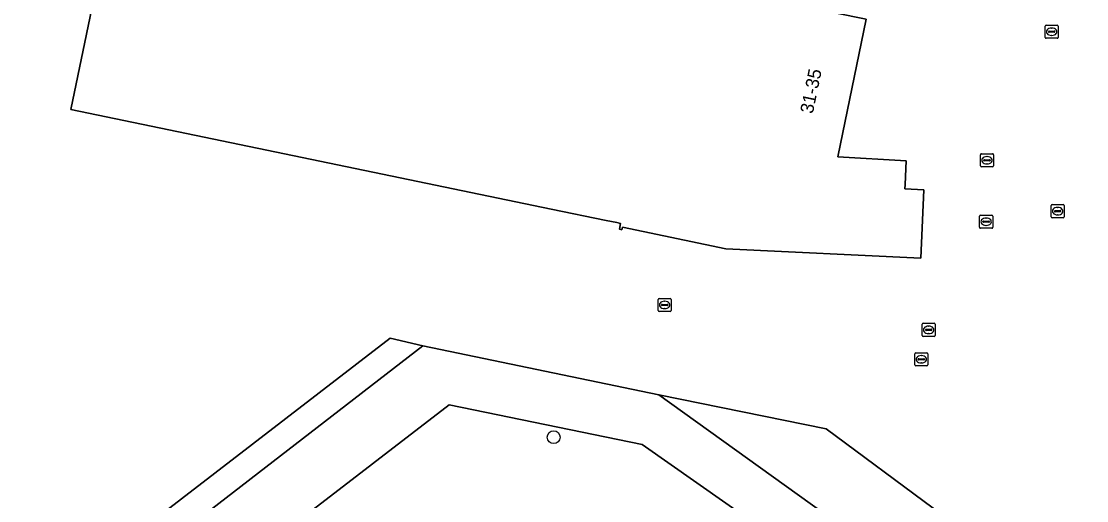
# Model space of a CAD drawing. Extents: x 157692 to 159674, y 381452 to 383291.
# Drawn here: x 158655.2 to 158736.3, y 381918.9 to 381955.5 of the extents above; entities that cross this region are included whole.
import ezdxf

# ---------------------------------------------------------------- set-up
doc = ezdxf.new("R2010")
doc.units = 0
for name, color, linetype in [('IMGEO_Boom', 7, 'Continuous'), ('IMGEO_Brandkraan', 7, 'Continuous'), ('IMGEO_Erf', 7, 'Continuous'), ('IMGEO_Groenvoorziening', 7, 'Continuous'), ('IMGEO_Hek', 7, 'Continuous'), ('IMGEO_Kolk', 7, 'Continuous'), ('IMGEO_Pand', 7, 'Continuous'), ('IMGEO_Pand_nummerreeks', 7, 'Continuous'), ('IMGEO_Rioolput', 7, 'Continuous'), ('IMGEO_Waterloop', 7, 'Continuous')]:
    doc.layers.add(name, color=color, linetype=linetype)

msp = doc.modelspace()

# ---------------------------------------------------------------- linework, layer by layer
at = {"layer": 'IMGEO_Boom'}
msp.add_circle((158695.725, 381923.769), 0.489, dxfattribs=at)
at = {"layer": 'IMGEO_Brandkraan'}
for p, q in [((158733.631, 381940.573), (158733.631, 381941.425)), ((158733.706, 381941.499), (158734.558, 381941.499)), ((158734.632, 381941.425), (158734.632, 381940.573)), ((158734.558, 381940.499), (158733.706, 381940.499)), ((158733.89, 381940.993), (158733.89, 381941.005)), ((158734.328, 381940.956), (158733.93, 381940.956)), ((158733.933, 381941.042), (158734.331, 381941.042)), ((158734.142, 381940.719), (158734.117, 381940.719)), ((158734.119, 381941.279), (158734.144, 381941.279)), ((158734.374, 381941.005), (158734.374, 381940.993))]:
    msp.add_line(p, q, dxfattribs=at)
for points in [[(158733.631, 381940.573), (158733.631, 381941.425)], [(158733.706, 381941.499), (158734.558, 381941.499)], [(158734.632, 381941.425), (158734.632, 381940.573)], [(158734.558, 381940.499), (158733.706, 381940.499)]]:
    msp.add_lwpolyline(points, dxfattribs=at)
for centre, radius, start, end in [((158733.708, 381941.423), 0.0765, 91.55205, 178.44795), ((158733.708, 381941.423), 0.0765, 91.55205, 178.44795), ((158734.556, 381941.423), 0.0765, 1.55205, 88.44795), ((158734.556, 381941.423), 0.0765, 1.55205, 88.44795), ((158733.708, 381940.575), 0.0765, 181.55205, 268.44795), ((158733.708, 381940.575), 0.0765, 181.55205, 268.44795), ((158733.93, 381941.002), 0.0403, 85.87752, 175.75265), ((158733.927, 381940.992), 0.0366, 178.93798, 274.71019), ((158734.331, 381940.999), 0.043, 264.86636, 352.45326), ((158734.335, 381941.004), 0.0386, 1.73085, 96.63898), ((158734.556, 381940.575), 0.0765, 271.55205, 358.44795), ((158734.556, 381940.575), 0.0765, 271.55205, 358.44795)]:
    msp.add_arc(centre, radius, start, end, dxfattribs=at)
for centre, major_axis, ratio, start_param, end_param in [((158734.118, 381940.999), (-0.387, 0.002), 0.722429, 4.712389, 7.853982), ((158734.143, 381940.999), (-0.39, 0.002), 0.717154, 1.570796, 4.712389)]:
    msp.add_ellipse(centre, major_axis=major_axis, ratio=ratio, start_param=start_param, end_param=end_param, dxfattribs=at)
at = {"layer": 'IMGEO_Erf'}
msp.add_lwpolyline([(158664.128, 381973.71), (158713.569, 381963.436), (158712.251, 381957.142), (158719.537, 381955.629), (158717.381, 381945.141), (158722.597, 381944.826), (158722.505, 381943.036), (158722.488, 381942.706), (158723.939, 381942.615), (158723.695, 381937.426), (158708.841, 381938.136), (158700.971, 381939.766), (158700.93, 381939.582), (158700.735, 381939.627), (158700.816, 381940.064), (158700.532, 381940.123), (158699.728, 381940.29), (158695.533, 381941.16), (158658.933, 381948.752)], close=True, dxfattribs=at)
msp.add_lwpolyline([(158624.725, 381886.233), (158683.269, 381931.316), (158685.758, 381930.737), (158703.73, 381926.995), (158716.491, 381924.398), (158724.647, 381918.357), (158745.17, 381903.414), (158763.626, 381917.95), (158795.014, 381942.671), (158804.708, 381950.306)], dxfattribs=at)
at = {"layer": 'IMGEO_Groenvoorziening'}
msp.add_lwpolyline([(158776.423, 381922.752), (158777.324, 381922.523), (158780.275, 381921.775), (158784.698, 381920.653), (158797.869, 381940.663), (158795.619, 381940.468), (158786.617, 381934.019), (158754.359, 381908.504), (158745.892, 381902.253), (158742.29, 381899.292), (158742.662, 381899.025), (158742.172, 381897.333), (158740.224, 381896.745), (158702.48, 381923.203), (158687.769, 381926.237), (158618.962, 381873.281)], dxfattribs=at)
for points in [[(158586.402, 381853.577), (158585.982, 381856.018), (158594.838, 381861.745), (158603.993, 381868.033), (158633.512, 381890.366), (158685.758, 381930.737), (158683.269, 381931.316), (158624.725, 381886.233), (158606.244, 381872.139), (158601.416, 381868.614), (158584.118, 381856.969)], [(158745.17, 381903.414), (158724.647, 381918.357), (158716.491, 381924.398), (158703.73, 381926.995), (158742.29, 381899.292)]]:
    msp.add_lwpolyline(points, close=True, dxfattribs=at)
at = {"layer": 'IMGEO_Hek'}
msp.add_lwpolyline([(158624.725, 381886.233), (158683.269, 381931.316)], dxfattribs=at)
at = {"layer": 'IMGEO_Kolk'}
for p, q in [((158733.174, 381954.248), (158733.174, 381955.1)), ((158733.249, 381955.174), (158734.101, 381955.174)), ((158734.175, 381955.1), (158734.175, 381954.248)), ((158733.433, 381954.668), (158733.433, 381954.68)), ((158733.871, 381954.631), (158733.473, 381954.631)), ((158733.476, 381954.717), (158733.874, 381954.717)), ((158733.685, 381954.394), (158733.66, 381954.394)), ((158733.662, 381954.954), (158733.687, 381954.954)), ((158733.917, 381954.68), (158733.917, 381954.668)), ((158734.101, 381954.174), (158733.249, 381954.174)), ((158728.182, 381939.766), (158728.182, 381940.618)), ((158728.257, 381940.692), (158729.109, 381940.692)), ((158728.67, 381940.472), (158728.695, 381940.472)), ((158729.183, 381940.618), (158729.183, 381939.766)), ((158729.109, 381939.692), (158728.257, 381939.692)), ((158728.441, 381940.186), (158728.441, 381940.198)), ((158728.879, 381940.149), (158728.481, 381940.149)), ((158728.484, 381940.235), (158728.882, 381940.235)), ((158728.693, 381939.912), (158728.668, 381939.912)), ((158728.925, 381940.198), (158728.925, 381940.186)), ((158703.684, 381933.423), (158703.684, 381934.275)), ((158703.759, 381934.349), (158704.611, 381934.349)), ((158704.172, 381934.129), (158704.197, 381934.129)), ((158704.685, 381934.275), (158704.685, 381933.423)), ((158704.611, 381933.349), (158703.759, 381933.349)), ((158703.943, 381933.843), (158703.943, 381933.855)), ((158704.381, 381933.806), (158703.983, 381933.806)), ((158703.986, 381933.892), (158704.384, 381933.892)), ((158704.195, 381933.569), (158704.17, 381933.569)), ((158704.427, 381933.855), (158704.427, 381933.843)), ((158723.24, 381929.278), (158723.24, 381930.13)), ((158723.315, 381930.204), (158724.167, 381930.204)), ((158723.728, 381929.984), (158723.753, 381929.984)), ((158724.241, 381930.13), (158724.241, 381929.278)), ((158724.167, 381929.204), (158723.315, 381929.204)), ((158723.499, 381929.698), (158723.499, 381929.71)), ((158723.937, 381929.661), (158723.539, 381929.661)), ((158723.542, 381929.747), (158723.94, 381929.747)), ((158723.751, 381929.424), (158723.726, 381929.424)), ((158723.983, 381929.71), (158723.983, 381929.698))]:
    msp.add_line(p, q, dxfattribs=at)
for points in [[(158733.174, 381954.248), (158733.174, 381955.1)], [(158733.249, 381955.174), (158734.101, 381955.174)], [(158734.175, 381955.1), (158734.175, 381954.248)], [(158734.101, 381954.174), (158733.249, 381954.174)], [(158728.182, 381939.766), (158728.182, 381940.618)], [(158728.257, 381940.692), (158729.109, 381940.692)], [(158729.183, 381940.618), (158729.183, 381939.766)], [(158729.109, 381939.692), (158728.257, 381939.692)], [(158703.684, 381933.423), (158703.684, 381934.275)], [(158703.759, 381934.349), (158704.611, 381934.349)], [(158704.685, 381934.275), (158704.685, 381933.423)], [(158704.611, 381933.349), (158703.759, 381933.349)], [(158723.24, 381929.278), (158723.24, 381930.13)], [(158723.315, 381930.204), (158724.167, 381930.204)], [(158724.241, 381930.13), (158724.241, 381929.278)], [(158724.167, 381929.204), (158723.315, 381929.204)]]:
    msp.add_lwpolyline(points, dxfattribs=at)
for centre, radius, start, end in [((158733.251, 381955.098), 0.0765, 91.55205, 178.44795), ((158733.251, 381955.098), 0.0765, 91.55205, 178.44795), ((158734.099, 381955.098), 0.0765, 1.55205, 88.44795), ((158734.099, 381955.098), 0.0765, 1.55205, 88.44795), ((158733.473, 381954.677), 0.0403, 85.87752, 175.75265), ((158733.47, 381954.667), 0.0366, 178.93798, 274.71019), ((158733.874, 381954.674), 0.043, 264.86636, 352.45326), ((158733.878, 381954.679), 0.0386, 1.73085, 96.63898), ((158733.251, 381954.25), 0.0765, 181.55205, 268.44795), ((158733.251, 381954.25), 0.0765, 181.55205, 268.44795), ((158734.099, 381954.25), 0.0765, 271.55205, 358.44795), ((158734.099, 381954.25), 0.0765, 271.55205, 358.44795), ((158728.259, 381940.616), 0.0765, 91.55205, 178.44795), ((158728.259, 381940.616), 0.0765, 91.55205, 178.44795), ((158729.107, 381940.616), 0.0765, 1.55205, 88.44795), ((158729.107, 381940.616), 0.0765, 1.55205, 88.44795), ((158728.259, 381939.768), 0.0765, 181.55205, 268.44795), ((158728.259, 381939.768), 0.0765, 181.55205, 268.44795), ((158728.481, 381940.195), 0.0403, 85.87752, 175.75265), ((158728.478, 381940.185), 0.0366, 178.93798, 274.71019), ((158728.882, 381940.192), 0.043, 264.86636, 352.45326), ((158728.886, 381940.197), 0.0386, 1.73085, 96.63898), ((158729.107, 381939.768), 0.0765, 271.55205, 358.44795), ((158729.107, 381939.768), 0.0765, 271.55205, 358.44795), ((158703.761, 381934.273), 0.0765, 91.55205, 178.44795), ((158703.761, 381934.273), 0.0765, 91.55205, 178.44795), ((158704.609, 381934.273), 0.0765, 1.55205, 88.44795), ((158704.609, 381934.273), 0.0765, 1.55205, 88.44795), ((158703.761, 381933.425), 0.0765, 181.55205, 268.44795), ((158703.761, 381933.425), 0.0765, 181.55205, 268.44795), ((158703.983, 381933.852), 0.0403, 85.87752, 175.75265), ((158703.98, 381933.842), 0.0366, 178.93798, 274.71019), ((158704.384, 381933.849), 0.043, 264.86636, 352.45326), ((158704.388, 381933.854), 0.0386, 1.73085, 96.63898), ((158704.609, 381933.425), 0.0765, 271.55205, 358.44795), ((158704.609, 381933.425), 0.0765, 271.55205, 358.44795), ((158723.317, 381930.128), 0.0765, 91.55205, 178.44795), ((158723.317, 381930.128), 0.0765, 91.55205, 178.44795), ((158724.165, 381930.128), 0.0765, 1.55205, 88.44795), ((158724.165, 381930.128), 0.0765, 1.55205, 88.44795), ((158723.317, 381929.28), 0.0765, 181.55205, 268.44795), ((158723.317, 381929.28), 0.0765, 181.55205, 268.44795), ((158723.539, 381929.707), 0.0403, 85.87752, 175.75265), ((158723.536, 381929.697), 0.0366, 178.93798, 274.71019), ((158723.94, 381929.704), 0.043, 264.86636, 352.45326), ((158723.944, 381929.709), 0.0386, 1.73085, 96.63898), ((158724.165, 381929.28), 0.0765, 271.55205, 358.44795), ((158724.165, 381929.28), 0.0765, 271.55205, 358.44795)]:
    msp.add_arc(centre, radius, start, end, dxfattribs=at)
for centre, major_axis, ratio, start_param, end_param in [((158733.661, 381954.674), (-0.387, 0.002), 0.722429, 4.712389, 7.853982), ((158733.686, 381954.674), (-0.39, 0.002), 0.717154, 1.570796, 4.712389), ((158728.669, 381940.192), (-0.387, 0.002), 0.722429, 4.712389, 7.853982), ((158728.694, 381940.192), (-0.39, 0.002), 0.717154, 1.570796, 4.712389), ((158704.171, 381933.849), (-0.387, 0.002), 0.722429, 4.712389, 7.853982), ((158704.196, 381933.849), (-0.39, 0.002), 0.717154, 1.570796, 4.712389), ((158723.727, 381929.704), (-0.387, 0.002), 0.722429, 4.712389, 7.853982), ((158723.752, 381929.704), (-0.39, 0.002), 0.717154, 1.570796, 4.712389)]:
    msp.add_ellipse(centre, major_axis=major_axis, ratio=ratio, start_param=start_param, end_param=end_param, dxfattribs=at)
at = {"layer": 'IMGEO_Pand'}
msp.add_lwpolyline([(158723.939, 381942.615), (158722.488, 381942.706), (158722.505, 381943.036), (158722.597, 381944.826), (158717.381, 381945.141), (158719.537, 381955.629), (158712.251, 381957.142), (158713.569, 381963.436), (158664.128, 381973.71), (158658.933, 381948.752), (158695.533, 381941.16), (158699.728, 381940.29), (158700.532, 381940.123), (158700.816, 381940.064), (158700.735, 381939.627), (158700.93, 381939.582), (158700.971, 381939.766), (158708.841, 381938.136), (158723.695, 381937.426)], close=True, dxfattribs=at)
at = {"layer": 'IMGEO_Rioolput'}
for p, q in [((158728.319, 381945.378), (158729.171, 381945.378)), ((158728.244, 381944.452), (158728.244, 381945.304)), ((158728.503, 381944.872), (158728.503, 381944.884)), ((158728.941, 381944.835), (158728.543, 381944.835)), ((158728.546, 381944.921), (158728.944, 381944.921)), ((158728.755, 381944.598), (158728.73, 381944.598)), ((158728.732, 381945.158), (158728.757, 381945.158)), ((158728.987, 381944.884), (158728.987, 381944.872)), ((158729.245, 381945.304), (158729.245, 381944.452)), ((158729.171, 381944.378), (158728.319, 381944.378)), ((158723.805, 381931.524), (158723.805, 381932.376)), ((158723.88, 381932.45), (158724.732, 381932.45)), ((158724.806, 381932.376), (158724.806, 381931.524)), ((158724.064, 381931.944), (158724.064, 381931.956)), ((158724.502, 381931.907), (158724.104, 381931.907)), ((158724.107, 381931.993), (158724.505, 381931.993)), ((158724.316, 381931.67), (158724.291, 381931.67)), ((158724.293, 381932.23), (158724.318, 381932.23)), ((158724.548, 381931.956), (158724.548, 381931.944)), ((158724.732, 381931.45), (158723.88, 381931.45))]:
    msp.add_line(p, q, dxfattribs=at)
for points in [[(158728.319, 381945.378), (158729.171, 381945.378)], [(158728.244, 381944.452), (158728.244, 381945.304)], [(158729.245, 381945.304), (158729.245, 381944.452)], [(158729.171, 381944.378), (158728.319, 381944.378)], [(158723.805, 381931.524), (158723.805, 381932.376)], [(158723.88, 381932.45), (158724.732, 381932.45)], [(158724.806, 381932.376), (158724.806, 381931.524)], [(158724.732, 381931.45), (158723.88, 381931.45)]]:
    msp.add_lwpolyline(points, dxfattribs=at)
for centre, radius, start, end in [((158728.321, 381945.302), 0.0765, 91.55205, 178.44795), ((158728.321, 381945.302), 0.0765, 91.55205, 178.44795), ((158729.169, 381945.302), 0.0765, 1.55205, 88.44795), ((158729.169, 381945.302), 0.0765, 1.55205, 88.44795), ((158728.543, 381944.881), 0.0403, 85.87752, 175.75265), ((158728.54, 381944.871), 0.0366, 178.93798, 274.71019), ((158728.944, 381944.878), 0.043, 264.86636, 352.45326), ((158728.948, 381944.883), 0.0386, 1.73085, 96.63898), ((158728.321, 381944.454), 0.0765, 181.55205, 268.44795), ((158728.321, 381944.454), 0.0765, 181.55205, 268.44795), ((158729.169, 381944.454), 0.0765, 271.55205, 358.44795), ((158729.169, 381944.454), 0.0765, 271.55205, 358.44795), ((158723.882, 381932.374), 0.0765, 91.55205, 178.44795), ((158723.882, 381932.374), 0.0765, 91.55205, 178.44795), ((158724.73, 381932.374), 0.0765, 1.55205, 88.44795), ((158724.73, 381932.374), 0.0765, 1.55205, 88.44795), ((158724.104, 381931.953), 0.0403, 85.87752, 175.75265), ((158724.101, 381931.943), 0.0366, 178.93798, 274.71019), ((158724.505, 381931.95), 0.043, 264.86636, 352.45326), ((158724.509, 381931.955), 0.0386, 1.73085, 96.63898), ((158723.882, 381931.526), 0.0765, 181.55205, 268.44795), ((158723.882, 381931.526), 0.0765, 181.55205, 268.44795), ((158724.73, 381931.526), 0.0765, 271.55205, 358.44795), ((158724.73, 381931.526), 0.0765, 271.55205, 358.44795)]:
    msp.add_arc(centre, radius, start, end, dxfattribs=at)
for centre, major_axis, ratio, start_param, end_param in [((158728.731, 381944.878), (-0.387, 0.002), 0.722429, 4.712389, 7.853982), ((158728.756, 381944.878), (-0.39, 0.002), 0.717154, 1.570796, 4.712389), ((158724.292, 381931.95), (-0.387, 0.002), 0.722429, 4.712389, 7.853982), ((158724.317, 381931.95), (-0.39, 0.002), 0.717154, 1.570796, 4.712389)]:
    msp.add_ellipse(centre, major_axis=major_axis, ratio=ratio, start_param=start_param, end_param=end_param, dxfattribs=at)
at = {"layer": 'IMGEO_Waterloop'}
msp.add_lwpolyline([(158586.402, 381853.577), (158588.772, 381851.999), (158605.532, 381863.102), (158618.962, 381873.281), (158687.769, 381926.237), (158702.48, 381923.203), (158740.224, 381896.745), (158742.172, 381897.333), (158742.662, 381899.025), (158742.29, 381899.292), (158703.73, 381926.995), (158685.758, 381930.737), (158633.512, 381890.366), (158603.993, 381868.033), (158594.838, 381861.745), (158585.982, 381856.018)], close=True, dxfattribs=at)

# ---------------------------------------------------------------- texts
at = {"layer": 'IMGEO_Pand_nummerreeks'}
msp.add_text('31-35', height=1, rotation=78.38363, dxfattribs=at).set_placement((158715.474, 381948.382))

doc.saveas('drawing.dxf')
